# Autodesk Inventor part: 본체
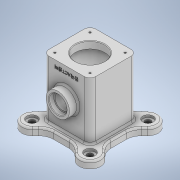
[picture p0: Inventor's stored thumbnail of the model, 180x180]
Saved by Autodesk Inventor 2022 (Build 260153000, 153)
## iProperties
Created: 2022-05
Part Number: 본체
Material: 일반
Document SubType Name: Modeling
Designer: Admin
Density: 1 g/cm^3
Appearance: 기본값
Author: Admin
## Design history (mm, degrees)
sketch "스케치1"
  geometry: L1 (49, 49)-(-49, 49); L2 (-49, 49)-(-49, -49); L3 (-49, -49)-(49, -49); L4 (49, -49)-(49, 49); L5 (49, 49)-(-49, -49); L6 (-49, 49)-(49, -49); L7 (49, -49)-(-49, 49); L8 (61.728, -36.272)-(-36.272, 61.728); L9 (-61.728, 36.272)-(36.272, -61.728); L10 (36.272, 61.728)-(-61.728, -36.272); L11 (-36.272, -61.728)-(61.728, 36.272); L12 (104.238, 0)-(-104.238, 0) reference; L13 (0, -104.238)-(0, 104.238) reference; A1 r 18 centre (49, -49) between (36.272, -61.728) and (61.728, -36.272); A2 r 18 centre (-49, 49) between (-36.272, 61.728) and (-61.728, 36.272); A3 r 18 centre (49, 49) between (61.728, 36.272) and (36.272, 61.728); A4 r 18 centre (-49, -49) between (-61.728, -36.272) and (-36.272, -61.728); 11 further points
  constraints: 24 end point, 8 point on circle, 8 tangent, 4 centre point, 4 midpoint, 3 perpendicular, 1 collinear
  dimensions: "d0" = 98 distance of L3.end L1.start; "d1" = 98 distance of L2.end L3.end; "d2" = 36 distance between parallel lines of L10 L11; "d3" = 36 distance between parallel lines of L9 L8; "d73" = 45 deg angle of L5 L13
extrude "돌출1" new body sketch "스케치1" distance "d4" = 12; taper "d5" = 0 deg
sketch "스케치2" dims "d6" = 140
  geometry: L1 (0, 0)-(-75.016, -75.016); L2 (-104.02, 0)-(99.003, 0) reference; L3 (0, 99.003)-(0, -104.02) reference; 2 further points
  constraints: 2 end point, 1 coincident, 1 point on line, 3 other
  dimensions: "d7" = 45 deg angle of L2 L1
hole "구멍1" sketch "스케치2" at (-49.497, -49.497) diameter "d9" = 10; stored, may be unused: countersink angle "d13" = 90 deg, drill point angle "d15" = 118 deg; dims "d10" = 8, "d11" = 18, "d12" = 4, "d14" = 11.8
sketch "스케치3"
  geometry: L1 (-40, -40)-(40, -40); L2 (40, -40)-(40, 40); L3 (40, 40)-(-40, 40); L4 (-40, 40)-(-40, -40); L5 (-40, -40)-(40, 40); L6 (40, -40)-(-40, 40); 1 further point
  constraints: 12 end point, 2 midpoint, 2 parallel, 1 horizontal, 1 perpendicular
  dimensions: "d16" = 80 distance of L2.end L3.end; "d17" = 80 distance of L3.end L1.start
extrude "돌출2" join sketch "스케치3" distance "d18" = 98; taper "d19" = 0 deg
node "작업 평면1"
sketch "스케치4"
  geometry: L1 (67, 12)-(36.272, 12) reference; C1 r 20 at (0, 61); 2 further points
  constraints: 1 centre point, 1 vertical alignment
  dimensions: "d21" = 40 diameter of C1; "d22" = 49 distance from line of L1 C1.centre
extrude "돌출3" join sketch "스케치4" stored distance "d23" = 98; taper "d24" = 0 deg
sketch "스케치5"
  geometry: L1 (110, 40)-(110, -40) reference; L2 (110, 25)-(98, 25); L3 (98, 25)-(98, 35); L4 (98, 35)-(12, 35); L5 (12, 35)-(12, 25); L6 (12, 25)-(0, 25); L7 (0, 23.544)-(0, -23.544) reference; L8 (-22, 0)-(132, 0) reference; L9 (110, 25)-(110, 0); L10 (110, 0)-(0, 0); L11 (0, 25)-(0, 0)
  constraints: 16 end point, 5 point on line, 4 perpendicular, 1 collinear, 1 midpoint, 1 vertical
  dimensions: "d25" = 12 distance of L2.start L2.end; "d26" = 12 distance of L5.end L6.end; "d27" = 70 diameter of L4 L8; "d28" = 50 diameter of L2 L8
revolve "회전1" sketch "스케치5" stored, may be unused: angle "d29" = 90 deg
sketch "스케치6"
  geometry: C1 r 20 at (0, 0) reference; 2 further points
  constraints: 1 coincident
hole "구멍2" sketch "스케치6" at (0, 0) diameter "d30" = 25; stored, may be unused: countersink angle "d34" = 90 deg, drill point angle "d36" = 118 deg; dims "d31" = 6, "d32" = 30, "d33" = 8, "d35" = 8
fillet "모깎기1" dims "d37" = 25
fillet "모깎기2" dims "d38" = 3
fillet "모깎기3" dims "d39" = 10
fillet "모깎기4" dims "d40" = 3
fillet "모깎기5" dims "d41" = 3
sketch "스케치7"
  geometry: L1 (-30, -30)-(30, -30); L2 (30, -30)-(30, 30); L3 (30, 30)-(-30, 30); L4 (-30, 30)-(-30, -30); L5 (-30, -30)-(30, 30); L6 (30, -30)-(-30, 30); C1 r 25 at (0, 0) reference; 5 further points
  constraints: 12 end point, 4 coincident, 2 midpoint, 2 parallel, 1 horizontal, 1 perpendicular
  dimensions: "d42" = 60 distance of L3.end L1.start; "d43" = 60 distance of L2.end L3.end
hole "구멍3" sketch "스케치7" at (-30, -30), (-30, 30), (30, -30), (30, 30) diameter "d44" = 3.242; stored, may be unused: countersink angle "d48" = 90 deg, drill point angle "d50" = 118 deg; dims "d45" = 8, "d46" = 4, "d47" = 2, "d49" = 10
sketch "스케치8"
  geometry: L1 (30, 30)-(-30, 30); L2 (-30, 30)-(-30, -30); L3 (-30, -30)-(30, -30); L4 (30, -30)-(30, 30); L5 (30, 30)-(-30, -30); L6 (-30, 30)-(30, -30); 5 further points
  constraints: 12 end point, 4 coincident, 2 midpoint, 2 parallel, 1 horizontal, 1 perpendicular
  dimensions: "d53" = 60 distance of L1.start L1.end; "d54" = 60 distance of L3.end L1.start
hole "구멍4" sketch "스케치8" at (30, 30), (30, -30), (-30, -30), (-30, 30) diameter "d55" = 3.242; stored, may be unused: countersink angle "d59" = 90 deg, drill point angle "d61" = 118 deg; dims "d56" = 8, "d57" = 4, "d58" = 2, "d60" = 10
chamfer "모따기1" distance "d62" = 1; stored, may be unused: second distance "d63" = 2, angle "d64" = 45 deg
fillet "모깎기6" dims "d65" = 3
sketch "스케치9"
  geometry: L1 (0, 0)-(60, 0) reference; C1 r 15 at (30, -49) reference; 2 further points
  constraints: 1 vertical alignment, 1 other
  dimensions: "d66" = 10 distance from line of L1 point (30, -10)
feature "엠보싱1" sketch "스케치9" dims "d0" = 98, "d1" = 98, "d2" = 36, "d3" = 36, "d9" = 10, "d11" = 18, "d12" = 4, "d14" = 11.8, "d67" = 0.5, "d68" = 0, "d73" = 45 deg
chamfer "모따기2" distance "d69" = 1; stored, may be unused: second distance "d70" = 2, angle "d71" = 45 deg
node "솔리드1"
mirror "미러1"
mirror "미러2"
feature "A9D066F2-1C7D-4E18-AEED-F7BC21143FA4" dims "d9" = 10, "d10" = 8, "d11" = 18, "d12" = 4, "d13" = 90 deg, "d14" = 11.8, "d15" = 118 deg
other parameters: "d20" = 55
